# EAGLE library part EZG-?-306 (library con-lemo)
LEMO Connector Source: http://www.lemo.com/pdfs/catalog/ROW/German/unipole_multipole.pdf
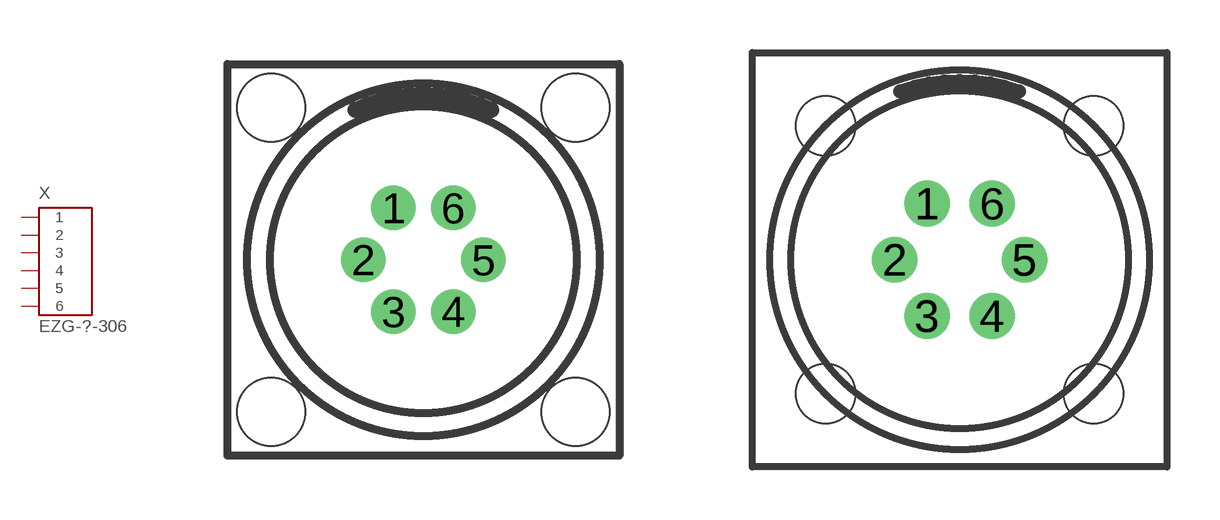
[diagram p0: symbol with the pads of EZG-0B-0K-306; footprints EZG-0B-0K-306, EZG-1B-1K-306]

Designator prefix X

## EZG-0B-306 (OC_FARNELL: unknown; OC_NEWARK: unknown)  [EZG-0B-0K-306]
1  1  pas
2  2  pas
3  3  pas
4  4  pas
5  5  pas
6  6  pas

## EZG-0K-306 (OC_FARNELL: unknown; OC_NEWARK: unknown)  [EZG-0B-0K-306]
Pads as for EZG-0B-0K-306

## EZG-1B-306 (OC_FARNELL: unknown; OC_NEWARK: unknown)  [EZG-1B-1K-306]
Pads as for EZG-0B-0K-306

## EZG-1K-306 (OC_FARNELL: unknown; OC_NEWARK: unknown)  [EZG-1B-1K-306]
Pads as for EZG-0B-0K-306

## EZG-2B-306 (OC_FARNELL: unknown; OC_NEWARK: unknown)  [EZG-2B-2K-306]
Pads as for EZG-0B-0K-306

## EZG-2K-306 (OC_FARNELL: unknown; OC_NEWARK: unknown)  [EZG-2B-2K-306]
Pads as for EZG-0B-0K-306

## Footprint EZG-0B-0K-306 (pad centres in mm)
LEMO Connector Source: http://www.lemo.com/pdfs/catalog/ROW/German/unipole_multipole.pdf
drill 0.6 pad 1.1 round: 1 -0.75,1.299; 2 -1.5,0; 3 -0.75,-1.299; 4 0.75,-1.299; 5 1.5,0; 6 0.75,1.299
hole 1.7 at -3.81,3.81
hole 1.7 at 3.81,3.81
hole 1.7 at 3.81,-3.81
hole 1.7 at -3.81,-3.81

## Footprint EZG-1B-1K-306 (pad centres in mm)
LEMO Connector Source: http://www.lemo.com/pdfs/catalog/ROW/German/unipole_multipole.pdf
drill 0.8 pad 1.3 round: 1 -0.925,1.602; 2 -1.85,0; 3 -0.925,-1.602; 4 0.925,-1.602; 5 1.85,0; 6 0.925,1.602
hole 1.7 at -3.81,3.81
hole 1.7 at 3.81,3.81
hole 1.7 at 3.81,-3.81
hole 1.7 at -3.81,-3.81

## Footprint EZG-2B-2K-306 (pad centres in mm)
LEMO Connector Source: http://www.lemo.com/pdfs/catalog/ROW/German/unipole_multipole.pdf
drill 0.8 pad 1.2 round: 1 0,2.8; 2 -2.663,0.865; 3 -1.646,-2.265; 4 1.646,-2.265; 5 2.663,0.865; 6 0,0
hole 1.7 at -5.08,5.08
hole 1.7 at 5.08,5.08
hole 1.7 at 5.08,-5.08
hole 1.7 at -5.08,-5.08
